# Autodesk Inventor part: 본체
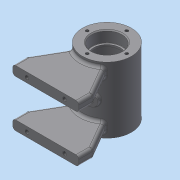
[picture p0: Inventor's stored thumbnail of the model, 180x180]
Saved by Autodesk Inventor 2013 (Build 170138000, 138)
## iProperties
Created: 2018-05
Part Number: 본체
Material: 일반
Document SubType Name: Modeling
Designer: dgall
Density: 1 g/cm^3
Author: dgall
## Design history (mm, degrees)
sketch "스케치1"
  geometry: C1 r 26 at (0, 0); 1 further point
  constraints: 1 centre point, 1 coincident
  dimensions: "d0" = 52 diameter of C1
extrude "돌출1" new body sketch "스케치1" distance "d1" = 70; taper "d2" = 0 deg
sketch "스케치2"
  geometry: L1 (26, 70)-(26, 0) reference; L2 (26, 0)-(-26, 0) reference; L3 (-26, 0)-(-26, 70) reference; L4 (-26, 70)-(26, 70) reference; L5 (0, 0)-(0, 70); L6 (16, 70)-(16, 58.3); L7 (15.7, 58)-(14, 58); L8 (14, 58)-(14, 56); L9 (14, 56)-(18, 56); L10 (21, 53)-(21, 17); L11 (18, 14)-(14, 14); L12 (14, 14)-(14, 12); L13 (14, 12)-(15.7, 12); L14 (16, 11.7)-(16, 0); L15 (16, 70)-(0, 70); L16 (16, 0)-(0, 0); A1 r 3 centre (18, 53) between (21, 53) and (18, 56); A2 r 3 centre (18, 17) between (18, 14) and (21, 17); A3 r 0.3 centre (15.7, 58.3) between (15.7, 58) and (16, 58.3); A4 r 0.3 centre (15.7, 11.7) between (16, 11.7) and (15.7, 12); 2 further points
  constraints: 24 end point, 8 point on circle, 8 tangent, 7 parallel, 6 point on line, 4 centre point, 3 collinear, 2 equal radius, 1 midpoint, 1 perpendicular
  dimensions: "d3" = 28 diameter of L8 L5; "d5" = 28 diameter of L12 L5; "d6" = 32 diameter of L6 L5; "d7" = 32 diameter of L14 L5; "d8" = 42 diameter of L10 L5; "d9" = 2 distance of L7.end L8.end; "d10" = 2 distance of L11.end L12.end; "d11" = 12 distance of L6.start point (16, 58); "d12" = 12 distance of point (16, 12) L14.end; "d13" = 3 radius of A1; "d14" = 0.3 radius of A3
revolve "회전1" sketch "스케치2" stored, may be unused: angle "d15" = 90 deg
chamfer "모따기1" distance "d16" = 1; stored, may be unused: second distance "d17" = 2, angle "d18" = 45 deg
node "작업 평면1"
node "작업 평면2"
sketch "스케치3"
  geometry: L1 (-35, -65)-(35, -65); L2 (-35, -65)-(-35, -50); L3 (-35, -50)-(-17.325, -19.386); L4 (35, -65)-(35, -50); L5 (35, -50)-(17.325, -19.386); C1 r 20.236 at (0, 0) reference; A1 r 26 centre (0, 0) between (-17.325, -19.386) and (17.325, -19.386) reference; 2 further points
  constraints: 10 end point, 2 point on circle, 1 horizontal, 1 midpoint, 1 parallel, 1 perpendicular, 1 vertical alignment
  dimensions: "d20" = 70 distance of L1.start L1.end; "d21" = 65 distance of point (0, 0) point (0, -65); "d22" = 15 distance of L1.start L2.end; "d23" = 15 distance of L1.end L4.end; "d24" = 30 deg angle of L4 L5; "d25" = 30 deg angle of L2 L3
extrude "돌출2" join sketch "스케치3" distance "d26" = 10; taper "d27" = 0 deg
fillet "모깎기1" dims "d28" = 3
fillet "모깎기2" dims "d29" = 3
node "작업 평면3"
sketch "스케치4"
  geometry: L1 (-35, -65)-(35, -65); L2 (-35, -65)-(-35, -50); L3 (-35, -50)-(-17.325, -19.386); L4 (35, -65)-(35, -50); L5 (35, -50)-(17.325, -19.386); C1 r 20.236 at (0, 0) reference; A1 r 26 centre (0, 0) between (-17.325, -19.386) and (17.325, -19.386) reference; 2 further points
  constraints: 10 end point, 2 point on circle, 1 horizontal, 1 midpoint, 1 parallel, 1 perpendicular, 1 vertical alignment
  dimensions: "d31" = 70 distance of L1.start L1.end; "d32" = 65 distance of point (0, -65) point (0, 0); "d33" = 15 distance of L1.start L2.end; "d34" = 15 distance of L1.end L4.end; "d35" = 30 deg angle of L2 L3; "d36" = 30 deg angle of L4 L5
extrude "돌출3" join sketch "스케치4" distance "d37" = 10; taper "d38" = 0 deg
fillet "모깎기3" dims "d39" = 3
fillet "모깎기4" dims "d40" = 3
fillet "모깎기5" dims "d41" = 3
fillet "모깎기6" dims "d42" = 3
node "작업 평면5"
  node "작업 평면4"
sketch "스케치5"
  geometry: L1 (26, 70)-(-26, 70) reference; C1 r 5 at (0, 35); 2 further points
  constraints: 1 centre point, 1 coincident, 1 vertical alignment
  dimensions: "d44" = 35 distance from line of point (0, 35) L1; "d45" = 10 diameter of C1
extrude "돌출4" join sketch "스케치5" stored distance "d46" = 10; taper "d47" = 0 deg
fillet "모깎기7" dims "d48" = 2
sketch "스케치6"
  geometry: C1 r 5 at (0, 0) reference; 1 further point
hole "구멍1" sketch "스케치6" at (0, 0) diameter "d49" = 5.188; stored, may be unused: countersink angle "d53" = 90 deg, drill point angle "d55" = 118 deg; dims "d50" = 6, "d51" = 4, "d52" = 2, "d54" = 8
sketch "스케치7"
  geometry: L1 (67, -43)-(67, -47) reference; 3 further points
  constraints: 1 horizontal alignment, 1 midpoint
  dimensions: "d56" = 20 horizontal distance of point (32, -55) point (52, -45)
hole "구멍2" sketch "스케치7" at (52, -45) diameter "d57" = 4.134; stored, may be unused: countersink angle "d61" = 90 deg, drill point angle "d63" = 118 deg; dims "d58" = 8, "d59" = 4, "d60" = 2, "d62" = 10
node "작업 평면6"
sketch "스케치8" dims "d64" = 42
  geometry: C1 r 17 at (0, 0) reference; 2 further points
  constraints: 2 vertical alignment, 1 coincident, 2 other
hole "구멍3" sketch "스케치8" at (0, 21) diameter "d65" = 3.242; stored, may be unused: countersink angle "d69" = 90 deg, drill point angle "d71" = 118 deg; dims "d66" = 8, "d67" = 4, "d68" = 2, "d70" = 10
sketch "스케치9"
  geometry: L1 (-17, 70)-(-16, 69) reference; L2 (-16, 69)-(-16, 58.3) reference; L3 (-15.7, 58)-(-14, 58) reference; L4 (-14, 58)-(-14, 56) reference; L5 (-14, 56)-(-18, 56) reference; L6 (-21, 53)-(-21, 17) reference; L7 (-18, 14)-(-14, 14) reference; L8 (-14, 14)-(-14, 12) reference; L9 (-14, 12)-(-15.7, 12) reference; L10 (-16, 11.7)-(-16, 1) reference; L11 (-16, 1)-(-17, 0) reference; L12 (-17, 0)-(-19.379, 0) reference; L13 (-19.379, 0)-(-19.379, 10) reference; L14 (-19.379, 10)-(-21, 10.974) reference; L15 (-21, 10.974)-(-22.621, 10) reference; L16 (-22.621, 10)-(-22.621, 0) reference; L17 (-22.621, 0)-(-26, 0) reference; L18 (-26, 0)-(-26, 70) reference; L19 (-26, 70)-(-22.621, 70) reference; L20 (-22.621, 70)-(-22.621, 60) reference; L21 (-22.621, 60)-(-21, 59.026) reference; L22 (-21, 59.026)-(-19.379, 60) reference; L23 (-19.379, 60)-(-19.379, 70) reference; L24 (-19.379, 70)-(-17, 70) reference; L25 (16, 69)-(17, 70) reference; L26 (17, 70)-(19.379, 70) reference; L27 (19.379, 70)-(19.379, 60) reference; L28 (19.379, 60)-(21, 59.026) reference; L29 (21, 59.026)-(22.621, 60) reference; L30 (22.621, 60)-(22.621, 70) reference; L31 (22.621, 70)-(26, 70) reference; L32 (26, 70)-(26, 0) reference; L33 (26, 0)-(22.621, 0) reference; L34 (22.621, 0)-(22.621, 10) reference; L35 (22.621, 10)-(21, 10.974) reference; L36 (21, 10.974)-(19.379, 10) reference; L37 (19.379, 10)-(19.379, 0) reference; L38 (19.379, 0)-(17, 0) reference; L39 (17, 0)-(16, 1) reference; L40 (16, 1)-(16, 11.7) reference; L41 (15.7, 12)-(14, 12) reference; L42 (14, 12)-(14, 14) reference; L43 (14, 14)-(18, 14) reference; L44 (21, 17)-(21, 53) reference; L45 (18, 56)-(14, 56) reference; L46 (14, 56)-(14, 58) reference; L47 (14, 58)-(15.7, 58) reference; L48 (16, 58.3)-(16, 69) reference; C1 r 6 at (0, 35); A1 r 0.3 centre (-15.7, 58.3) between (-16, 58.3) and (-15.7, 58) reference; A2 r 3 centre (-18, 53) between (-18, 56) and (-21, 53) reference; A3 r 3 centre (-18, 17) between (-21, 17) and (-18, 14) reference; A4 r 0.3 centre (-15.7, 11.7) between (-15.7, 12) and (-16, 11.7) reference; A5 r 0.3 centre (15.7, 11.7) between (16, 11.7) and (15.7, 12) reference; A6 r 3 centre (18, 17) between (18, 14) and (21, 17) reference; A7 r 3 centre (18, 53) between (21, 53) and (18, 56) reference; A8 r 0.3 centre (15.7, 58.3) between (15.7, 58) and (16, 58.3) reference; 1 further point
  constraints: 1 centre point, 1 vertical alignment
  dimensions: "d75" = 12 diameter of C1; "d76" = 35 distance of point (0, 0) C1.centre
  node "절단 모서리 투영4"
sketch "스케치10"
  geometry: L1 (-5, 27.111)-(-5, 29) reference; L2 (-5, 29)-(-2.594, 29) reference; L3 (-2.594, 29)-(-2.594, 20.839) reference; L4 (2.594, 20.839)-(2.594, 29) reference; L5 (2.594, 29)-(5, 29) reference; L6 (5, 29)-(5, 27.111) reference; L7 (-32, -65)-(32, -65) reference; L8 (0, 0)-(0, -65); L9 (0, 0)-(9.919, -27.251); L10 (9.919, -27.251)-(4.28, -29.303); L11 (4.28, -29.303)-(3.014, -25.825); A1 r 26 centre (0, 0) between (-6.5, 25.174) and (6.5, 25.174) reference; A2 r 21 centre (0, 0) between (-2.594, 20.839) and (2.594, 20.839) reference; A3 r 26 centre (0, 0) between (6.5, 25.174) and (-6.5, 25.174); A4 r 26 centre (0, 0) between (3.014, -25.825) and (8.893, -24.432); 1 further point
  constraints: 8 end point, 5 point on circle, 2 centre point, 2 perpendicular, 1 coincident, 1 midpoint, 1 point on line, 4 other
  dimensions: "d77" = 20 deg angle of L8 L9; "d78" = 29 distance of L9.end point (0, 0); "d82" = 6 distance between parallel lines of L11 L9
  node "절단 모서리 투영5"
node "작업 평면7"
sketch "스케치11"
  geometry: L1 (25.081, 23)-(25.081, 27) reference; C1 r 6 at (0, 0); 1 further point
  constraints: 1 centre point
  dimensions: "d79" = 12 diameter of C1; "d80" = 25.08142 distance from line of L1 C1.centre; "d81" = 35 vertical distance of point (-9.919, -35) C1.centre
revolve "회전2" stored, may be unused: angle "d83" = 90 deg
fillet "모깎기8" dims "d84" = 2
sketch "스케치12"
  geometry: C1 r 6 at (0, 0) reference; 1 further point
hole "구멍4" sketch "스케치12" at (0, 0) diameter "d85" = 5.188; stored, may be unused: countersink angle "d89" = 90 deg, drill point angle "d91" = 118 deg; dims "d86" = 8, "d87" = 4, "d88" = 2, "d90" = 10
node "작업 평면8"
sketch "스케치13"
  geometry: L1 (-26, 0)-(26, 0) reference; L2 (-26, 0)-(-26, 70) reference; 2 further points
  constraints: 1 other
  dimensions: "d92" = 35 distance from line of point (0, 35) L1; "d93" = 26 distance from line of L2 point (0, 35)
feature "엠보싱1" sketch "스케치13" dims "d0" = 52, "d94" = 0.5, "d95" = 0
node "솔리드1"
mirror "대칭1"
mirror "대칭2"
pattern_circular "원형 패턴1" dims angle "d73" = 360 deg
mirror "대칭3"
node "절단 모서리 투영1"
node "절단 모서리 투영2"
node "절단 모서리 투영3"
other parameters: "d43" = 3
